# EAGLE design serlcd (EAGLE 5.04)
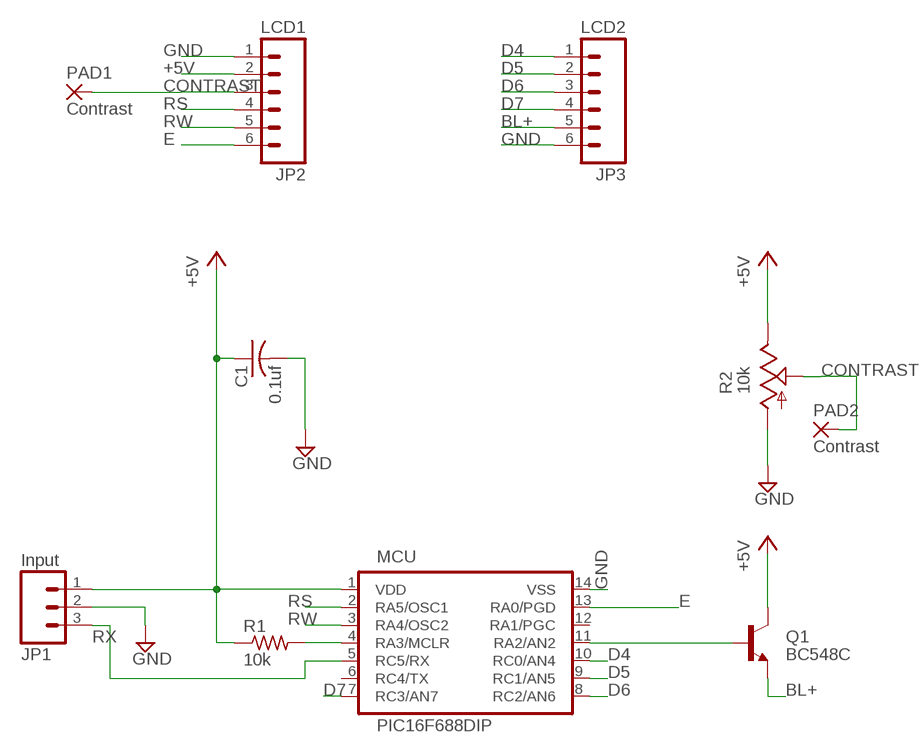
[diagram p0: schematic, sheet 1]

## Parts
C1  0.1uf  C-US025-030X050  [C025-030X050]
JP1  Input  M03LOCK_LONGPADS  [1X03_LOCK_LONGPADS]
JP2  LCD1  M06SIP  [1X06]
JP3  LCD2  M06SIP  [1X06]
MCU  PIC16F688DIP  [DIP-14]
PAD1  Contrast  WIREPAD1,6/0,8  [1,6/0,8]
PAD2  Contrast  WIREPAD1,6/0,8  [1,6/0,8]
Q1  BC548C  TRANSISTOR_NPNTO92  [TO-92]
R1  10k  R-US_0207/7  [0207/7]
R2  10k  POT-TRIM-PARALLAX  [POT-TRIM-PARALLAX]

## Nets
+5V: C1.1 JP1.1 JP2.2 MCU.1(VDD) Q1.3(C) R1.1 R2.3(E)
BL+: JP3.5 Q1.1(E)
CONTRAST: JP2.3 PAD1.1(P) PAD2.1(P) R2.2(S)
D4: JP3.1 MCU.10(RC0/AN4)
D5: JP3.2 MCU.9(RC1/AN5)
D6: JP3.3 MCU.8(RC2/AN6)
D7: JP3.4 MCU.7(RC3/AN7)
E: JP2.6 MCU.13(RA0/PGD)
GND: C1.2 JP1.2 JP2.1 JP3.6 MCU.14(VSS) R2.1(A)
N$1: MCU.11(RA2/AN2) Q1.2(B)
N$4: MCU.4(RA3/MCLR) R1.2
RS: JP2.4 MCU.2(RA5/OSC1)
RW: JP2.5 MCU.3(RA4/OSC2)
RX: JP1.3 MCU.5(RC5/RX)
Unconnected: MCU.6(RC4/TX) MCU.12(RA1/PGC)

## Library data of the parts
C1 = rcl:C-US: CAPACITOR, American symbol
JP1 = SparkFun:M03: Header 3 Standard 3-pin 0.1" header. Use with straight break away headers (SKU : PRT-00116), right angle break away headers (PRT-00553), swiss pins (PRT-00743), machine pins (PRT-00117), and female headers (PRT-00115). Molex polarized connector foot print use with SKU : PRT-08232 with associated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
JP2 JP3 = SparkFun:M06: Header 6 Standard 6-pin 0.1" header. Use with straight break away headers (SKU : PRT-00116), right angle break away headers (PRT-00553), swiss pins (PRT-00743), machine pins (PRT-00117), and female headers (PRT-00115). Molex polarized connector foot print use with SKU : PRT-08094 with associated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
MCU = trl:PIC16F688: PIC 16F688 8-Bit PIC16F88
PAD1 PAD2 = wirepad:WIREPAD: Wire PAD connect wire on PCB
Q1 = SparkFun:TRANSISTOR_NPN: Transistor NPN BJT configuration in SOT23 package. MMBT2222 is the common NPN we use. Double check BCE configuration again layout.
R1 = resistor:R-US_: RESISTOR, American symbol
R2 = trl:POT-TRIM-PARALLAX: POTENTIOMETER

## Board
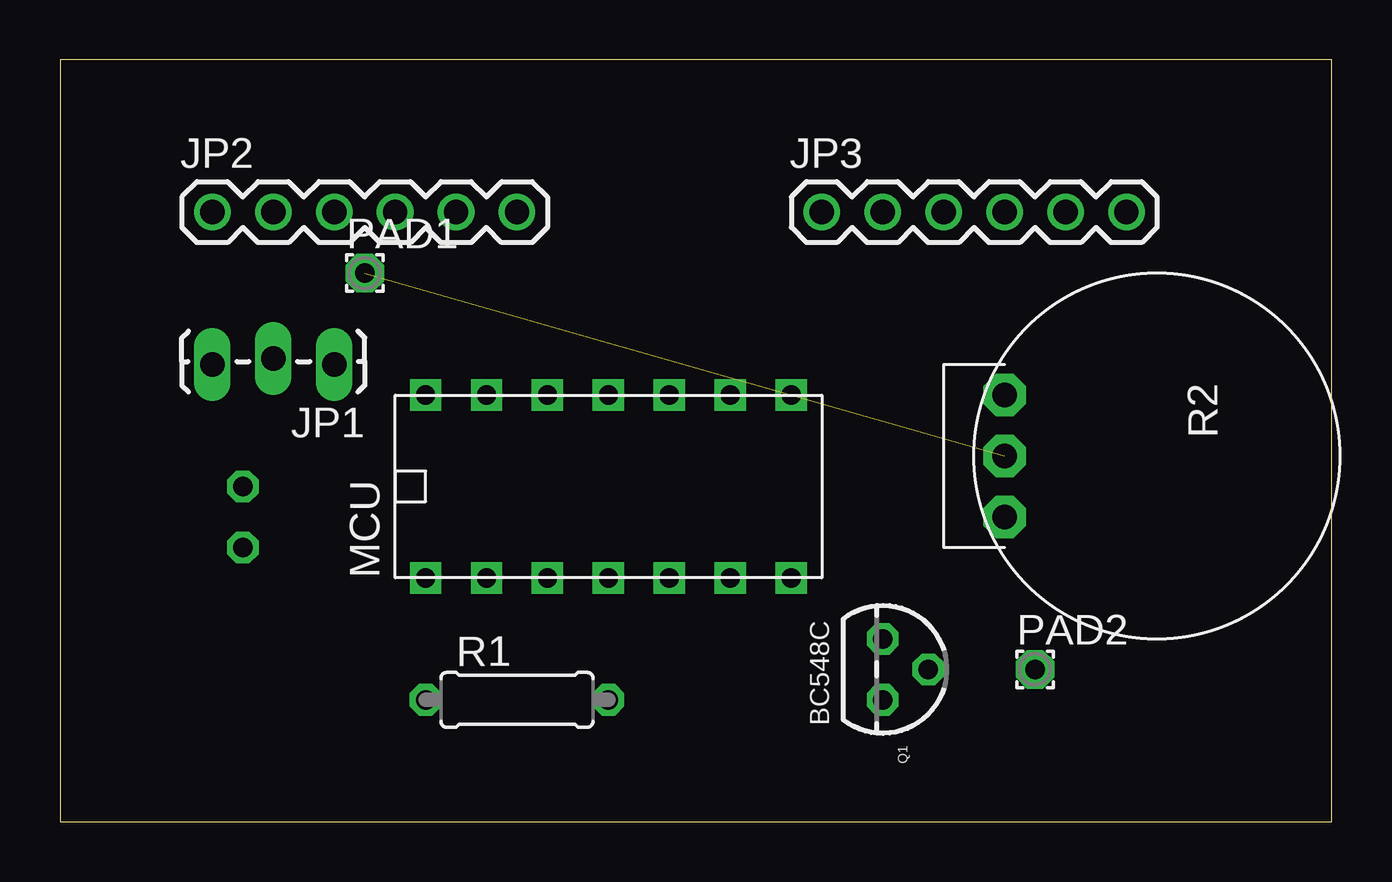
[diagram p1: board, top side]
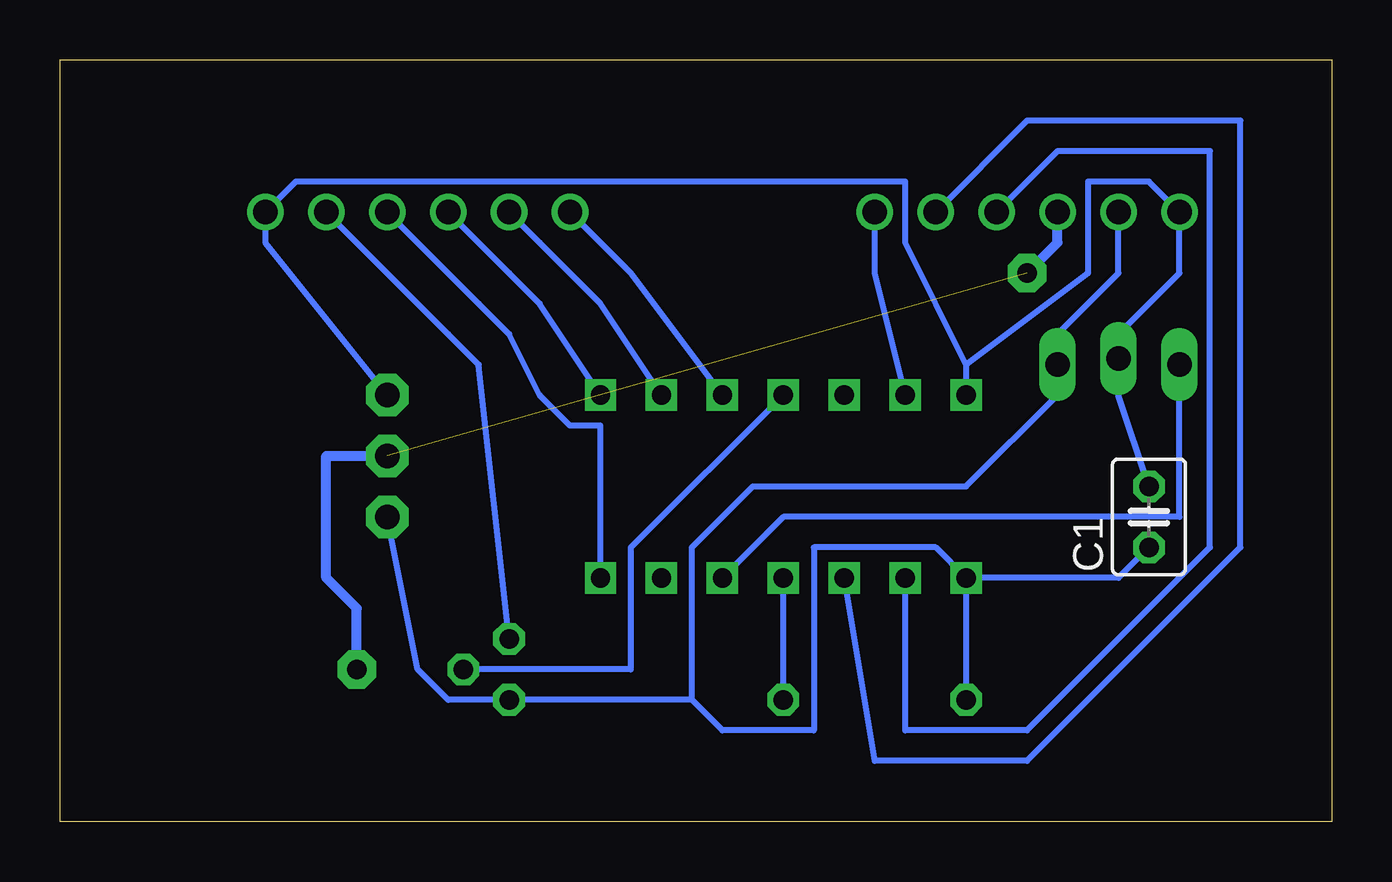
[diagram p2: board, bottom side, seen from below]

Size 53.01 x 31.74 mm. Coordinates in mm from the lower left corner, seen from the top.
Outline: 0,0 53.01,0 53.01,31.74 0,31.74 0,0
Copper layers (1*16): Top 0.035mm / dielectric 1.5mm / Bottom 0.035mm
Design rules "default": minimum track width 10mil, minimum drill 24mil, track to track 8mil, track to pad 8mil, pad to pad 8mil, via to via 8mil, smd to smd 8mil, copper to edge 40mil, drill to drill 8mil, minimum pad ring 10mil, minimum via ring 8mil, stop-mask expansion 4mil, vias tented up to drill 0mil, thermal gap 10mil

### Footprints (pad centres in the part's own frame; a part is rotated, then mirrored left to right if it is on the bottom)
C025-030X050 = drill 0.813 octagon: 1 -1.27,0; 2 1.27,0
1X03_LOCK_LONGPADS = drill 1.016 long: 1 0,0; 2 2.54,-0.254; 3 5.08,0
1X06 = drill 1.016 round: 1 0,0; 2 2.54,0; 3 5.08,0; 4 7.62,0; 5 10.16,0; 6 12.7,0
DIP-14 = drill 0.8 square: 1 -3.81,7.62; 2 -3.81,5.08; 3 -3.81,2.54; 4 -3.81,0; 5 -3.81,-2.54; 6 -3.81,-5.08; 7 -3.81,-7.62; 8 3.81,-7.62; 9 3.81,-5.08; 10 3.81,-2.54; 11 3.81,0; 12 3.81,2.54; 13 3.81,5.08; 14 3.81,7.62
1,6/0,8 = drill 0.813 pad 1.6 octagon: 1 0,0
TO-92 = drill 0.813 octagon: 1 -1.27,0; 2 0,1.905; 3 1.27,0
0207/7 = drill 0.813 octagon: 1 -3.81,0; 2 3.81,0
POT-TRIM-PARALLAX = drill 1.016 pad 1.778 octagon: 1 -2.54,-3.81; 2 0,-3.81; 3 2.54,-3.81

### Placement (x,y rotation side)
C1  7.62,12.7 90 bottom
JP1  11.43,19.05 180 top
JP2  6.35,25.4 0 top
JP3  31.75,25.4 0 top
MCU  22.86,13.97 90 top
PAD1  12.7,22.86 0 top
PAD2  40.64,6.35 0 top
Q1  34.29,6.35 270 top
R1  19.05,5.08 0 top
R2  43.18,15.24 270 top

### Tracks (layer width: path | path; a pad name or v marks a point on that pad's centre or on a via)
+5V
  Bottom 0.254: MCU.1 R1.1 | C1.1 8.89,10.16 MCU.1 | JP2.2 8.89,22.86 11.43,20.32 JP1.1 11.43,17.78 15.24,13.97 24.13,13.97 26.67,11.43 26.67,5.08 | R2.3 38.1,6.35 36.83,5.08 Q1.3 26.67,5.08 | MCU.1 16.51,11.43 21.59,11.43 21.59,3.81 25.4,3.81 26.67,5.08
BL+
  Bottom 0.254: Q1.1 35.56,19.05 36.83,20.32 JP3.5
CONTRAST  (1 unrouted)
  Bottom 0.406: PAD1.1 11.43,24.13 JP2.3 | PAD2.1 40.64,8.89 41.91,10.16 41.91,15.24 R2.2
D4
  Bottom 0.254: MCU.10 29.21,22.86 JP3.1
D5
  Bottom 0.254: MCU.9 30.48,21.59 33.02,24.13 JP3.2
D6
  Bottom 0.254: MCU.8 33.02,21.59 34.29,22.86 JP3.3
D7
  Bottom 0.254: MCU.7 30.48,16.51 31.75,16.51 33.02,17.78 34.29,20.32 35.56,21.59 JP3.4
E
  Bottom 0.254: MCU.13 19.05,22.86 19.05,24.13 JP2.6
GND
  Bottom 0.254: R2.1 44.45,24.13 JP3.6 43.18,26.67 17.78,26.67 17.78,24.13 15.24,19.05 | C1.2 8.89,17.78 8.89,19.05 JP1.2 8.89,20.32 6.35,22.86 JP2.1 7.62,26.67 10.16,26.67 10.16,22.86 15.24,19.05 | 15.24,19.05 MCU.14
N$1
  Bottom 0.254: MCU.11 29.21,11.43 29.21,6.35 35.56,6.35 Q1.2
N$4
  Bottom 0.254: R1.2 MCU.4
RS
  Bottom 0.254: MCU.2 17.78,3.81 12.7,3.81 5.08,11.43 5.08,27.94 11.43,27.94 JP2.4
RW
  Bottom 0.254: MCU.3 19.05,2.54 12.7,2.54 3.81,11.43 3.81,29.21 12.7,29.21 JP2.5
RX
  Bottom 0.254: MCU.5 22.86,12.7 6.35,12.7 6.35,17.78 JP1.3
